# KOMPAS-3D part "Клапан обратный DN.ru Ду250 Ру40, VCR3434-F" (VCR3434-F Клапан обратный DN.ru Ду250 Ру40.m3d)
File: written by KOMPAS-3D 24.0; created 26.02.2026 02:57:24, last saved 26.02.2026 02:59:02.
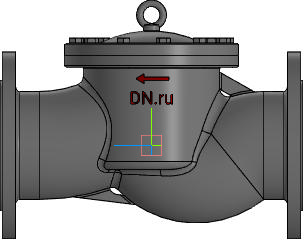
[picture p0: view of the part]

Document properties: Автор: R2D2; Полное имя файла: VCR3434-F Клапан обратный DN.ru Ду250 Ру40.cdw

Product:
- Part/product: Клапан обратный DN.ru Ду250 Ру40  | designation VCR3434-F
    Масса: 235
    Раздел спецификации: Прочие изделия
    Форматы листов документа: A2
    Примечание: D100-04062
    additional columns: D100-04062

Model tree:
1. Операция без истории:2

Referenced files in C:\Program Files\ASCON\KOMPAS-3D v24\Libs\EasySteel\: Rolled metal.kle, StandartSolutions.kle, DSTVProperties.lpt
Referenced files in C:\Program Files\ASCON\KOMPAS-3D v24\Templates\: Констр. чертеж А3 гориз. перв. лист.cdt
Referenced files in C:\Program Files\ASCON\KOMPAS-3D v24\Libs\EasySteel\BeltEndings\: 
Referenced files in C:\Program Files\ASCON\KOMPAS-3D v24\Libs\EasySteel\Punctures\: 
Referenced files in C:\Program Files\ASCON\KOMPAS-3D v24\Libs\EasySteel\Insulations\: 
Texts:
  Уголок равнополочный по ГОСТ 8509-93 (Спец)
  config2DpacketName
  config2DstdSizeID
  Констр. чертеж А3 гориз. перв. лист.cdt
  Болт ГОСТ 22353-77
  Шайба ГОСТ 22355-77
  Гайка ГОСТ 22354-77
  Нормальная пружинная шайба ГОСТ 6402-70 (исп. 1)
  SeaRox SL 436
  Точка начала. Х
  Точка начала. Y
  Точка начала. Z
  VCR3434-F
